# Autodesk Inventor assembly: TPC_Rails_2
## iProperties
Shininess: 64.0
Length Units: 11272
Angle Units: 11279
Time Units: 11290
Mass Units: 11286
Length Display Precision: 3
Angle Display Precision: 2
Compacted: True
Part Number: TPC_Rails_2
Document SubType Name: Assembly
Created: 2004-08
Designer: Lori
Manufacturer: Standard
Standards Organization: Custom
Density: 0.0
Volumn: 0.0
Area: 0.0
PropertySet Name: Model Information
Control State: 0
Master: False
Checked Out: False
Author: Lori
